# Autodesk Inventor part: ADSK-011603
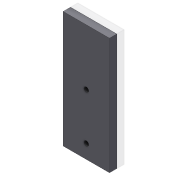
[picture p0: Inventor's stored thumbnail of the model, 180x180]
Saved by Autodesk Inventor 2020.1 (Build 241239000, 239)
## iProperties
Created: 2000-03
Part Number: ADSK-011603
Material: Pearson HRS
Document SubType Name: Modeling
Designer: glanglot
Density: 7.83 g/cm^3
Appearance: Métal - Acier
Mass: 790.094 g
Surface Area: 250.688 cm^2
Volume: 100.906 cm^3
Control State: 0
Master: False
Checked Out: False
Shininess: 0.0
Length Units: 11269
Angle Units: 11279
Time Units: 11290
Mass Units: 11283
Length Display Precision: 3
Angle Display Precision: 2
Compacted: True
Cutlength: 6.25
Material Desc: FLAT,HRS,0.38 X 2.5
Material_Number: A084404
Dimensions: 63,5x160x10 mm
Mass: 0,79 kg
Density: 0.0
Volumn: 0.0
Area: 0.0
PropertySet Name: Model Information
Author: glanglot
Revision Number: -
Title: ADSK-011603
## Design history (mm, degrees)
node "Solide1"
  node "Extrusion1" dims "d4" = 10, "d5" = 0
  node "Hole1" dims "d6" = 6.647, "d7" = 9.525, "d8" = 6.35, "d9" = 60 deg, "d10" = 19.05, "d11" = 118 deg, "d13" = 16
sketch "Sketch1"
  geometry: L1 (-31.75, -80)-(31.75, -80); L2 (31.75, -80)-(31.75, 80); L3 (31.75, 80)-(-31.75, 80); L4 (-31.75, 80)-(-31.75, -80); L5 (0, 80)-(0, -80); 4 further points
  constraints: 10 end point, 3 midpoint, 2 parallel, 2 point on line, 1 horizontal, 1 horizontal alignment, 1 perpendicular, 1 vertical alignment
  dimensions: "d0" = 160 distance between parallel lines of L1 L3; "d1" = 63.5 distance between parallel lines of L2 L4; "d2" = 20 distance from line of point (0, -60) L1; "d12" = 64 distance of point (0, -60) point (0, 4)
node "Corps solides"
node "Corps surfaciques"
